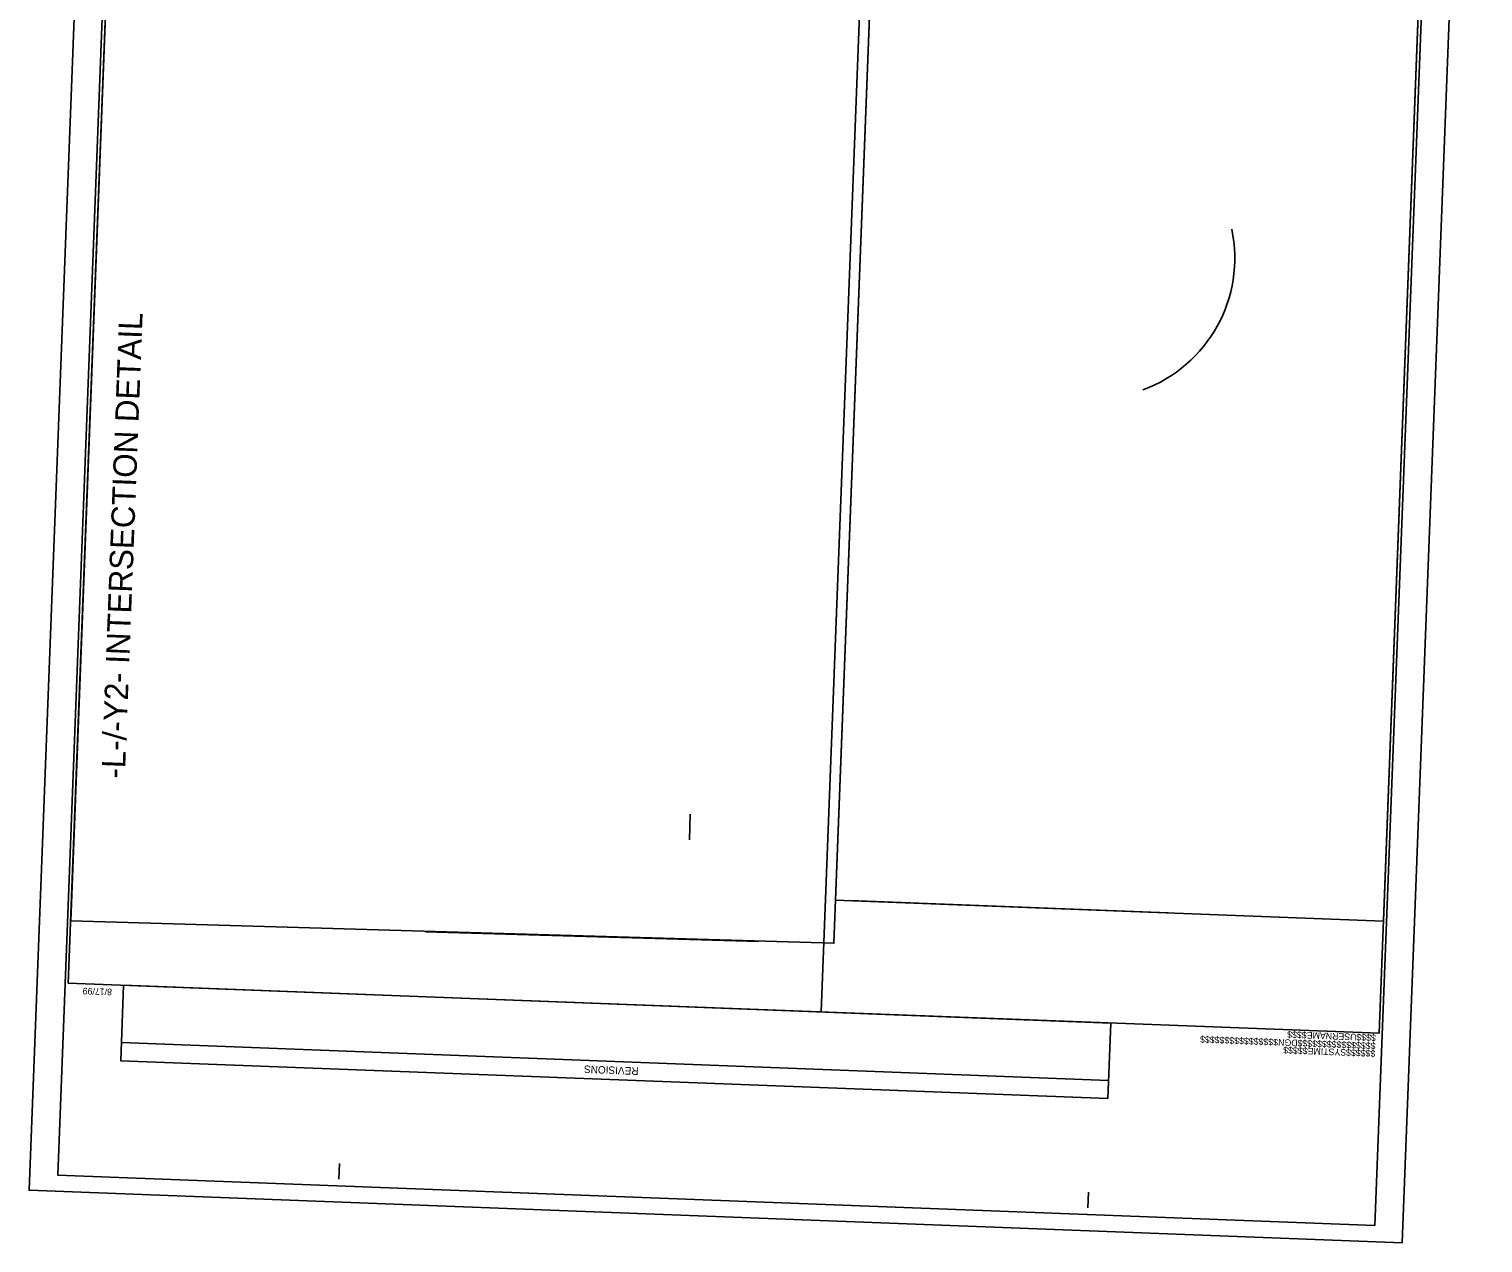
# Model space of a CAD drawing. Extents: x 2097521 to 2097987, y 686521 to 687299.
# Drawn here: x 2097521.5 to 2097987, y 686521.2 to 686910 of the extents above; entities that cross this region are included whole.
import ezdxf

# ---------------------------------------------------------------- set-up
doc = ezdxf.new("R2010")
doc.units = 0
for name, color, linetype in [('Default', 7, 'Continuous'), ('Matchline', 7, 'Continuous'), ('Prop Dimension', 7, 'Continuous'), ('Prop EOT', 7, 'Continuous'), ('Sheet Block Revision CELL', 7, 'Continuous'), ('Sheet Layout Plan Border', 7, 'Continuous'), ('Sheet Plan And Profile CELL', 7, 'Continuous'), ('Sheet Plan CELL', 7, 'Continuous'), ('Sheet Plot Border Inside CELL', 7, 'Continuous'), ('Sheet Plot Border Outside CELL', 7, 'Continuous'), ('Sheet Profile CELL', 7, 'Continuous'), ('Sheet Profile Grid Major CELL', 7, 'Continuous')]:
    doc.layers.add(name, color=color, linetype=linetype)

msp = doc.modelspace()

# ---------------------------------------------------------------- linework, layer by layer
at = {"layer": 'Default'}
msp.add_line((2097732.94, 686650.28), (2097733.18, 686658.46), dxfattribs=at)
at = {"layer": 'Matchline'}
for p, q in [((2097784.27, 686630.81), (2097886.19, 686626.9)), ((2097648.42, 686620.82), (2097755.04, 686617.72))]:
    msp.add_line(p, q, dxfattribs=at)
at = {"layer": 'Prop EOT'}
msp.add_arc((2097862.51, 686836.61), 45, 290.1891, 11.8817, dxfattribs=at)
at = {"layer": 'Sheet Block Revision CELL'}
msp.add_line((2097867.06, 686573.2), (2097551.04, 686585.32), dxfattribs=at)
msp.add_lwpolyline([(2097866.84, 686567.39), (2097550.81, 686579.51), (2097551.74, 686603.71), (2097867.77, 686591.59)], close=True, dxfattribs=at)
at = {"layer": 'Sheet Layout Plan Border'}
for points in [[(2097779.69, 686630.99), (2097798.86, 687130.62), (2097974.25, 687123.89), (2097955.08, 686624.26)], [(2097534.78, 686624.29), (2097553.94, 687123.99), (2097611.01, 687121.8), (2097611.07, 687123.23), (2097798.3, 687116.05), (2097794.51, 687017.17), (2097779.16, 686617.13)]]:
    msp.add_lwpolyline(points, close=True, dxfattribs=at)
at = {"layer": 'Sheet Plot Border Inside CELL'}
msp.add_lwpolyline([(2097952.36, 686526.7), (2097977.91, 687192.81), (2097556.18, 687208.99), (2097530.63, 686542.88)], close=True, dxfattribs=at)
at = {"layer": 'Sheet Plot Border Outside CELL'}
msp.add_lwpolyline([(2097961.14, 686521.16), (2097986.95, 687194.27), (2097547.28, 687211.13), (2097521.46, 686538.02)], close=True, dxfattribs=at)
at = {"layer": 'Sheet Profile CELL'}
for p, q in [((2097798.1, 687194.7), (2097775.11, 686595.14)), ((2097953.71, 686588.3), (2097976.7, 687187.85)), ((2097953.71, 686588.3), (2097953.71, 686588.3)), ((2097953.71, 686588.3), (2097953.71, 686588.3)), ((2097953.71, 686588.3), (2097953.71, 686588.3)), ((2097953.71, 686588.3), (2097953.71, 686588.3)), ((2097953.71, 686588.3), (2097953.71, 686588.3)), ((2097953.71, 686588.3), (2097953.71, 686588.3)), ((2097953.71, 686588.3), (2097953.71, 686588.3)), ((2097620.67, 686541.62), (2097620.86, 686546.62)), ((2097860.5, 686532.43), (2097860.69, 686537.42))]:
    msp.add_line(p, q, dxfattribs=at)
msp.add_lwpolyline([(2097557.01, 687203.95), (2097534.01, 686604.39), (2097953.71, 686588.3), (2097976.7, 687187.85)], close=True, dxfattribs=at)
msp.add_lwpolyline([(2097954.28, 686603.28), (2097954.28, 686603.28)], dxfattribs=at)
at = {"layer": 'Sheet Profile Grid Major CELL'}
msp.add_line((2097943.71, 686588.68), (2097943.71, 686588.68), dxfattribs=at)

# ---------------------------------------------------------------- texts
at = {"layer": 'Prop Dimension'}
msp.add_text('-L-/-Y2- INTERSECTION DETAIL', height=7.5, rotation=87.8037, dxfattribs=at).set_placement((2097552.11, 686669.79))
at = {"layer": 'Sheet Block Revision CELL'}
msp.add_text('REVISIONS', height=2.4, rotation=177.8037, dxfattribs=at).set_placement((2097716.65, 686577.35))
at = {"layer": 'Sheet Plan And Profile CELL'}
msp.add_text('8/17/99', height=2.1, rotation=177.8037, dxfattribs=at).set_placement((2097548.03, 686602.55))
at = {"layer": 'Sheet Plan CELL'}
for s, p in [('$$$$$$$$$$$$$$$$DGN$$$$$$$$$$$$$$$$', (2097952.64, 686585.28)), ('$$$$USERNAME$$$$', (2097952.74, 686587.9)), ('$$$$$$SYSTIME$$$$$', (2097952.56, 686582.85))]:
    msp.add_text(s, height=2.1, rotation=177.8037, dxfattribs=at).set_placement(p)

doc.saveas('drawing.dxf')
